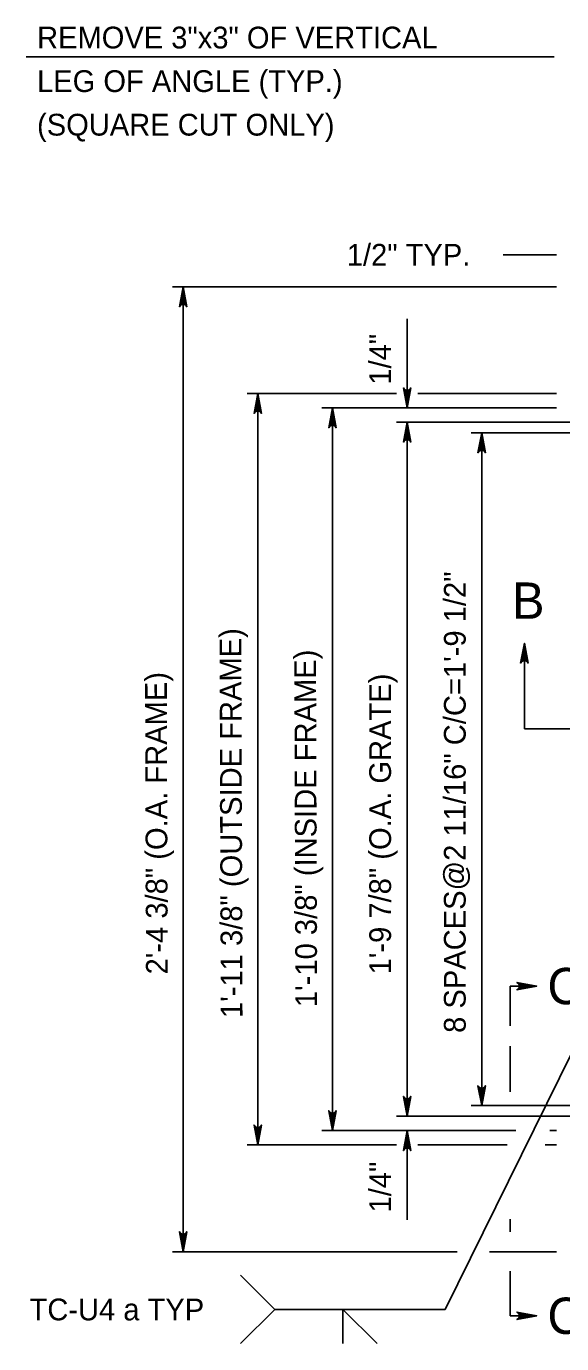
# Model space of a CAD drawing. Extents: x 0.71 to 8.05, y -5.67 to 4.31.
# Drawn here: x 0.708 to 2.185, y 0.293 to 3.921 of the extents above; entities that cross this region are included whole.
import ezdxf

# ---------------------------------------------------------------- set-up
doc = ezdxf.new("R2010")
doc.units = 0
for name, color, linetype in [('DETL-DIMS', 7, 'Continuous'), ('DETL-NOTE', 7, 'Continuous'), ('DETL-TITL', 7, 'Continuous')]:
    doc.layers.add(name, color=color, linetype=linetype)

msp = doc.modelspace()

# ---------------------------------------------------------------- linework, layer by layer
at = {"layer": 'DETL-DIMS'}
for p, q in [((0.708, 3.8374), (2.1634, 3.8374)), ((2.0228, 3.2918), (2.1698, 3.2918)), ((2.1698, 3.2036), (1.111, 3.2036)), ((1.1404, 0.546), (1.1404, 3.2036)), ((1.7581, 2.8701), (1.7581, 3.1154)), ((1.7286, 2.9095), (1.3169, 2.9095)), ((1.3463, 0.8401), (1.3463, 2.9095)), ((2.1698, 2.9095), (1.7875, 2.9095)), ((2.1698, 2.8701), (1.5228, 2.8701)), ((1.5522, 0.8795), (1.5522, 2.8701)), ((2.5913, 2.8307), (1.7286, 2.8307)), ((1.7581, 0.9189), (1.7581, 2.8307)), ((2.6302, 2.8013), (1.9345, 2.8013)), ((1.9639, 0.9483), (1.9639, 2.8013)), ((2.0816, 1.9865), (2.0816, 2.2218)), ((2.0816, 1.9865), (2.3051, 1.9865)), ((2.1159, 1.2776), (2.0423, 1.2776)), ((2.0423, 1.2776), (2.0423, 1.1681)), ((1.8636, 0.3868), (2.2488, 1.1658)), ((2.0423, 1.1124), (2.0423, 0.9863)), ((2.6302, 0.9483), (1.9345, 0.9483)), ((2.5928, 0.9189), (1.7286, 0.9189)), ((2.0582, 0.8795), (1.5228, 0.8795)), ((1.7581, 0.6342), (1.7581, 0.8795)), ((2.1698, 0.8795), (2.1515, 0.8795)), ((1.7286, 0.8401), (1.3169, 0.8401)), ((2.0339, 0.8401), (1.7875, 0.8401)), ((2.1698, 0.8401), (2.1393, 0.8401)), ((2.0423, 0.6356), (2.0423, 0.6004)), ((1.896, 0.546), (1.111, 0.546)), ((2.1698, 0.546), (1.9852, 0.546)), ((2.0423, 0.4928), (2.0423, 0.3695)), ((1.393, 0.3868), (1.6754, 0.3868)), ((1.5813, 0.2927), (1.5813, 0.3868)), ((1.5813, 0.3868), (1.6754, 0.2927)), ((1.6754, 0.3868), (1.8636, 0.3868)), ((2.1159, 0.3695), (2.0423, 0.3695))]:
    msp.add_line(p, q, dxfattribs=at)
for points in [[(1.1404, 3.2036), (1.1507, 3.1488), (1.1478, 3.153), (1.1441, 3.1552), (1.1404, 3.1558), (1.1367, 3.1552), (1.1331, 3.153), (1.1301, 3.1488), (1.1404, 3.2036), (1.1331, 3.153), (1.1367, 3.1552), (1.1404, 3.2036), (1.1404, 3.1558), (1.1441, 3.1552), (1.1404, 3.2036), (1.1478, 3.153)], [(1.3463, 2.9095), (1.3566, 2.8547), (1.3536, 2.8589), (1.35, 2.8611), (1.3463, 2.8617), (1.3426, 2.8611), (1.3389, 2.8589), (1.336, 2.8547), (1.3463, 2.9095), (1.3389, 2.8589), (1.3426, 2.8611), (1.3463, 2.9095), (1.3463, 2.8617), (1.35, 2.8611), (1.3463, 2.9095), (1.3536, 2.8589)], [(1.7581, 2.8701), (1.7478, 2.9249), (1.7507, 2.9207), (1.7544, 2.9185), (1.7581, 2.9179), (1.7617, 2.9185), (1.7654, 2.9207), (1.7683, 2.9249), (1.7581, 2.8701), (1.7654, 2.9207), (1.7617, 2.9185), (1.7581, 2.8701), (1.7581, 2.9179), (1.7544, 2.9185), (1.7581, 2.8701), (1.7507, 2.9207)], [(1.5522, 2.8701), (1.5625, 2.8153), (1.5595, 2.8195), (1.5558, 2.8217), (1.5522, 2.8223), (1.5485, 2.8217), (1.5448, 2.8195), (1.5419, 2.8153), (1.5522, 2.8701), (1.5448, 2.8195), (1.5485, 2.8217), (1.5522, 2.8701), (1.5522, 2.8223), (1.5558, 2.8217), (1.5522, 2.8701), (1.5595, 2.8195)], [(1.7581, 2.8307), (1.7683, 2.7758), (1.7654, 2.7801), (1.7617, 2.7822), (1.7581, 2.7829), (1.7544, 2.7822), (1.7507, 2.7801), (1.7478, 2.7758), (1.7581, 2.8307), (1.7507, 2.7801), (1.7544, 2.7822), (1.7581, 2.8307), (1.7581, 2.7829), (1.7617, 2.7822), (1.7581, 2.8307), (1.7654, 2.7801)], [(1.9639, 2.8013), (1.9742, 2.7464), (1.9713, 2.7507), (1.9676, 2.7528), (1.9639, 2.7535), (1.9603, 2.7528), (1.9566, 2.7507), (1.9537, 2.7464), (1.9639, 2.8013), (1.9566, 2.7507), (1.9603, 2.7528), (1.9639, 2.8013), (1.9639, 2.7535), (1.9676, 2.7528), (1.9639, 2.8013), (1.9713, 2.7507)], [(2.0816, 2.2218), (2.0919, 2.167), (2.0889, 2.1712), (2.0853, 2.1734), (2.0816, 2.174), (2.0779, 2.1734), (2.0742, 2.1712), (2.0713, 2.167), (2.0816, 2.2218), (2.0742, 2.1712), (2.0779, 2.1734), (2.0816, 2.2218), (2.0816, 2.174), (2.0853, 2.1734), (2.0816, 2.2218), (2.0889, 2.1712)], [(2.1159, 1.2776), (2.061, 1.2673), (2.0653, 1.2702), (2.0674, 1.2739), (2.0681, 1.2776), (2.0674, 1.2812), (2.0653, 1.2849), (2.061, 1.2878), (2.1159, 1.2776), (2.0653, 1.2849), (2.0674, 1.2812), (2.1159, 1.2776), (2.0681, 1.2776), (2.0674, 1.2739), (2.1159, 1.2776), (2.0653, 1.2702)], [(1.9639, 0.9483), (1.9537, 1.0031), (1.9566, 0.9989), (1.9603, 0.9967), (1.9639, 0.9961), (1.9676, 0.9967), (1.9713, 0.9989), (1.9742, 1.0031), (1.9639, 0.9483), (1.9713, 0.9989), (1.9676, 0.9967), (1.9639, 0.9483), (1.9639, 0.9961), (1.9603, 0.9967), (1.9639, 0.9483), (1.9566, 0.9989)], [(1.7581, 0.9189), (1.7478, 0.9737), (1.7507, 0.9695), (1.7544, 0.9673), (1.7581, 0.9667), (1.7617, 0.9673), (1.7654, 0.9695), (1.7683, 0.9737), (1.7581, 0.9189), (1.7654, 0.9695), (1.7617, 0.9673), (1.7581, 0.9189), (1.7581, 0.9667), (1.7544, 0.9673), (1.7581, 0.9189), (1.7507, 0.9695)], [(1.5522, 0.8795), (1.5419, 0.9343), (1.5448, 0.9301), (1.5485, 0.9279), (1.5522, 0.9273), (1.5558, 0.9279), (1.5595, 0.9301), (1.5625, 0.9343), (1.5522, 0.8795), (1.5595, 0.9301), (1.5558, 0.9279), (1.5522, 0.8795), (1.5522, 0.9273), (1.5485, 0.9279), (1.5522, 0.8795), (1.5448, 0.9301)], [(1.3463, 0.8401), (1.336, 0.8949), (1.3389, 0.8907), (1.3426, 0.8885), (1.3463, 0.8879), (1.35, 0.8885), (1.3536, 0.8907), (1.3566, 0.8949), (1.3463, 0.8401), (1.3536, 0.8907), (1.35, 0.8885), (1.3463, 0.8401), (1.3463, 0.8879), (1.3426, 0.8885), (1.3463, 0.8401), (1.3389, 0.8907)], [(1.7581, 0.8795), (1.7683, 0.8247), (1.7654, 0.8289), (1.7617, 0.8311), (1.7581, 0.8317), (1.7544, 0.8311), (1.7507, 0.8289), (1.7478, 0.8247), (1.7581, 0.8795), (1.7507, 0.8289), (1.7544, 0.8311), (1.7581, 0.8795), (1.7581, 0.8317), (1.7617, 0.8311), (1.7581, 0.8795), (1.7654, 0.8289)], [(1.1404, 0.546), (1.1301, 0.6008), (1.1331, 0.5966), (1.1367, 0.5944), (1.1404, 0.5938), (1.1441, 0.5944), (1.1478, 0.5966), (1.1507, 0.6008), (1.1404, 0.546), (1.1478, 0.5966), (1.1441, 0.5944), (1.1404, 0.546), (1.1404, 0.5938), (1.1367, 0.5944), (1.1404, 0.546), (1.1331, 0.5966)], [(1.2989, 0.4809), (1.393, 0.3868), (1.2989, 0.2927)], [(2.1159, 0.3695), (2.061, 0.3592), (2.0653, 0.3621), (2.0674, 0.3658), (2.0681, 0.3695), (2.0674, 0.3732), (2.0653, 0.3768), (2.061, 0.3798), (2.1159, 0.3695), (2.0653, 0.3768), (2.0674, 0.3732), (2.1159, 0.3695), (2.0681, 0.3695), (2.0674, 0.3658), (2.1159, 0.3695), (2.0653, 0.3621)]]:
    msp.add_lwpolyline(points, dxfattribs=at)

# ---------------------------------------------------------------- texts
at = {"layer": 'DETL-NOTE'}
for s, p in [('REMOVE 3"x3" OF VERTICAL ', (0.7377, 3.8601)), ('LEG OF ANGLE (TYP.)', (0.7377, 3.7401)), ('(SQUARE CUT ONLY)', (0.7377, 3.6201)), ('1/2" TYP.', (1.592, 3.2618)), ('TC-U4 a TYP', (0.717, 0.3568))]:
    msp.add_text(s, height=0.06, dxfattribs=at).set_placement(p)
for s, rotation, p in [('1/4"', 90, (1.7139, 2.934)), ('8 SPACES@2 11/16" C/C=1\'-9 1/2"', 90, (1.9198, 1.1486)), ('1\'-11 3/8" (OUTSIDE FRAME)', 90.1812, (1.3043, 1.1898)), ('1\'-10 3/8" (INSIDE FRAME)', 90.1812, (1.5101, 1.2198)), ('2\'-4 3/8" (O.A. FRAME)', 90.1812, (1.0981, 1.3098)), ('1\'-9 7/8" (O.A. GRATE)', 90, (1.7139, 1.3098)), ('1/4"', 90, (1.7139, 0.654))]:
    msp.add_text(s, height=0.06, rotation=rotation, dxfattribs=at).set_placement(p)
at = {"layer": 'DETL-TITL'}
for s, p in [('B', (2.0479, 2.2892)), ('C', (2.1453, 1.2276)), ('C', (2.1453, 0.3195))]:
    msp.add_text(s, height=0.1, dxfattribs=at).set_placement(p)

doc.saveas('drawing.dxf')
